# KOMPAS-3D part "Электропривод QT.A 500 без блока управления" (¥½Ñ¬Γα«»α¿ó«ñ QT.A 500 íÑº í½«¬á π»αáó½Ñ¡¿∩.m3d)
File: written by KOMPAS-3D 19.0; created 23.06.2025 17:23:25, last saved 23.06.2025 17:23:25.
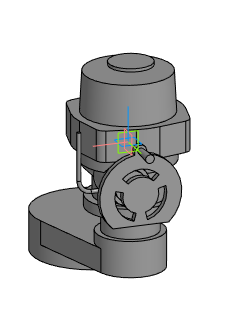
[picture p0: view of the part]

Document properties: Автор: Евгений; Полное имя файла: E:\Dendor Работа Сачек\3D для проектировщиков\3.5 Тип QT.А Электропривод\stp_Электропривод QT.A без блока управления\Электропривод QT.A 500 без блока управления.m3d

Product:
- Part/product: Электропривод QT.A 500 без блока управления

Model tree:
1. Операция без истории:1  (labels: Электропривод QT.A 500 без блока управления)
